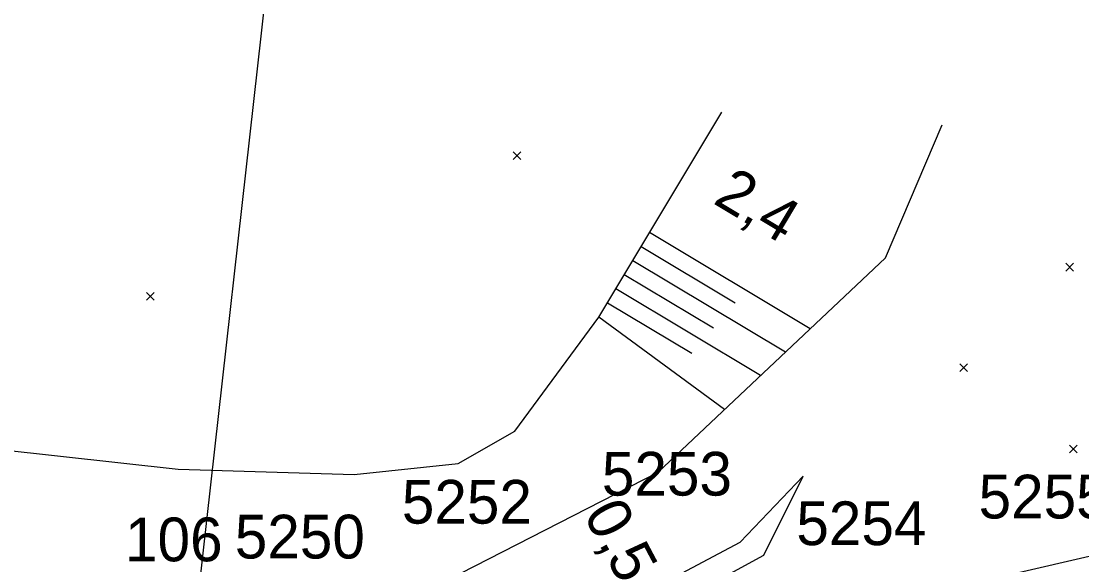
# Model space of a CAD drawing. Extents: x -804899 to -803847, y -1165742 to -1164942.
# Drawn here: x -804789.9 to -804741.39, y -1165100.4 to -1165075.55 of the extents above; entities that cross this region are included whole.
import ezdxf

# ---------------------------------------------------------------- set-up
doc = ezdxf.new("R2010")
doc.units = 0
for name, color, linetype in [('0381KM061-064P - Vrstva 48', 7, 'Continuous'), ('0381KM061-064P - Vrstva 49', 7, 'Continuous'), ('0381KM061-064P - Vrstva 51', 7, 'Continuous'), ('0381KM061-064P - Vrstva 8', 7, 'Continuous'), ('szdc - szdc_cislo', 7, 'Continuous'), ('TZ - TZ_cislo', 7, 'Continuous')]:
    doc.layers.add(name, color=color, linetype=linetype)

msp = doc.modelspace()

# ---------------------------------------------------------------- linework, layer by layer
at = {"layer": '0381KM061-064P - Vrstva 48'}
for p, q in [((-804753.817, -1165089.617), (-804761.161, -1165085.217)), ((-804757.249, -1165088.435), (-804761.547, -1165085.86)), ((-804754.951, -1165090.686), (-804761.932, -1165086.504)), ((-804758.238, -1165089.591), (-804762.318, -1165087.147)), ((-804756.086, -1165091.755), (-804762.703, -1165087.79)), ((-804759.227, -1165090.747), (-804763.089, -1165088.434)), ((-804757.736, -1165093.31), (-804763.474, -1165089.077))]:
    msp.add_line(p, q, dxfattribs=at)
at = {"layer": '0381KM061-064P - Vrstva 49'}
for p, q in [((-804767.043, -1165081.875), (-804767.397, -1165081.521)), ((-804767.043, -1165081.521), (-804767.397, -1165081.875)), ((-804741.772, -1165086.971), (-804742.126, -1165086.617)), ((-804741.772, -1165086.617), (-804742.126, -1165086.971)), ((-804783.822, -1165088.304), (-804784.176, -1165087.95)), ((-804783.822, -1165087.95), (-804784.176, -1165088.304)), ((-804746.616, -1165091.562), (-804746.97, -1165091.208)), ((-804746.616, -1165091.208), (-804746.97, -1165091.562)), ((-804741.6, -1165095.286), (-804741.954, -1165094.932)), ((-804741.6, -1165094.932), (-804741.954, -1165095.286))]:
    msp.add_line(p, q, dxfattribs=at)
for points in [[(-804769.918, -1165095.766), (-804767.328, -1165094.301), (-804763.474, -1165089.077), (-804757.859, -1165079.705)], [(-804782.933, -1165100.952), (-804770.452, -1165101.128), (-804760.766, -1165096.165), (-804750.377, -1165086.376), (-804747.774, -1165080.287)], [(-804834.138, -1165089.824), (-804812.848, -1165092.564), (-804796.393, -1165094.52), (-804782.729, -1165096.032), (-804774.669, -1165096.277), (-804769.918, -1165095.766)], [(-804778.125, -1165109.25), (-804771.874, -1165106.665), (-804764.298, -1165103.24), (-804757.01, -1165099.37), (-804754.139, -1165096.348)], [(-804764.444, -1165104.598), (-804755.942, -1165099.957), (-804754.139, -1165096.348)]]:
    msp.add_lwpolyline(points, dxfattribs=at)
at = {"layer": '0381KM061-064P - Vrstva 51'}
msp.add_lwpolyline([(-804799.401, -1165124.127), (-804788.787, -1165123.564), (-804781.178, -1165122.085), (-804777.377, -1165120.679), (-804772.772, -1165118.025), (-804766.254, -1165113.723), (-804759.193, -1165108.078), (-804752.39, -1165104.15), (-804745.737, -1165101.091), (-804737.367, -1165099.155), (-804728.561, -1165098.534)], dxfattribs=at)
at = {"layer": '0381KM061-064P - Vrstva 8'}
msp.add_line((-804782.747, -1165110.241), (-804774.889, -1165040.201), dxfattribs=at)

# ---------------------------------------------------------------- texts
at = {"layer": '0381KM061-064P - Vrstva 48'}
for s, rotation, p in [('2,4', 329.0731, (-804758.312, -1165083.848)), ('0,5', 297.9687, (-804764.215, -1165098.091))]:
    msp.add_text(s, height=2, rotation=rotation, dxfattribs=at).set_placement(p)
at = {"layer": 'szdc - szdc_cislo'}
for s, p in [('5253', (-804763.343, -1165097.24)), ('5252', (-804772.491, -1165098.523)), ('5255', (-804746.112, -1165098.286)), ('5254', (-804754.448, -1165099.506)), ('5250', (-804780.132, -1165100.116))]:
    msp.add_text(s, height=2, dxfattribs=at).set_placement(p)
at = {"layer": 'TZ - TZ_cislo'}
msp.add_text('106', height=2, dxfattribs=at).set_placement((-804785.152, -1165100.243))

doc.saveas('drawing.dxf')
